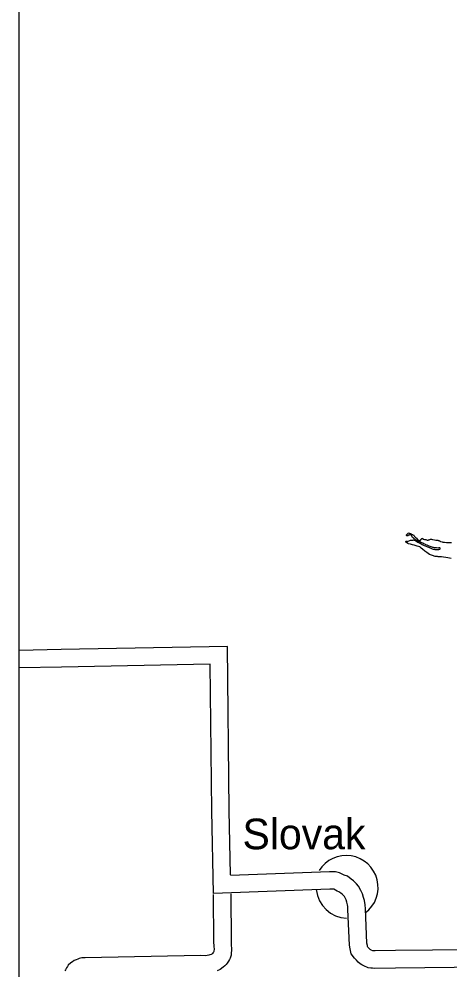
# Model space of a CAD drawing. Extents: x 982240 to 1103002, y 974866 to 1054902.
# Drawn here: x 984683 to 990254, y 1035077 to 1047369 of the extents above; entities that cross this region are included whole.
import ezdxf

# ---------------------------------------------------------------- set-up
doc = ezdxf.new("R2010")
doc.units = 0
for name, color, linetype in [('Level 10', 7, 'Continuous'), ('Level 24', 7, 'Continuous'), ('Level 9', 7, 'Continuous'), ('R_Draft', 7, 'Continuous')]:
    doc.layers.add(name, color=color, linetype=linetype)

msp = doc.modelspace()

# ---------------------------------------------------------------- linework, layer by layer
at = {"layer": 'Level 10'}
for points in [[(987416, 1036306), (987401, 1037140), (987377, 1039260), (985227, 1039218), (984683, 1039207)], [(987195, 1036066), (987176, 1037136), (987155, 1039031), (985231, 1038993), (984683, 1038982)], [(991462, 1035348), (989548, 1035328), (989285, 1035324), (989269, 1035325), (989255, 1035326), (989237, 1035333), (989232, 1035336), (989230, 1035337), (989222, 1035344), (989205, 1035360), (989193, 1035373), (989188, 1035380), (989186, 1035392), (989180, 1035424), (989160, 1035866), (989159, 1035920), (989149, 1035975), (989136, 1036015), (989124, 1036060), (989103, 1036106), (989073, 1036160), (989046, 1036189), (989009, 1036229), (988977, 1036251), (988928, 1036289), (988886, 1036304), (988826, 1036335), (988775, 1036345), (988698, 1036345), (987416, 1036299)], [(991451, 1035122), (989551, 1035103), (989278, 1035098), (989254, 1035100), (989233, 1035101), (989198, 1035105), (989140, 1035130), (989116, 1035143), (989092, 1035159), (989068, 1035180), (989045, 1035203), (989020, 1035229), (988978, 1035287), (988965, 1035349), (988956, 1035400), (988935, 1035859), (988935, 1035898), (988931, 1035920), (988920, 1035952), (988912, 1035984), (988903, 1036003), (988890, 1036026), (988881, 1036036), (988861, 1036058), (988844, 1036069), (988819, 1036089), (988797, 1036097), (988752, 1036120), (988701, 1036120), (987195, 1036066)], [(987194, 1036053), (987199, 1035432), (987201, 1035393), (987203, 1035375), (987204, 1035350), (987205, 1035342), (987202, 1035327), (987202, 1035316), (987196, 1035306), (987194, 1035302), (987185, 1035292), (987180, 1035285), (987174, 1035281), (987168, 1035278), (987151, 1035273), (987135, 1035268), (987135, 1035268), (987115, 1035265), (987091, 1035262), (987031, 1035265), (985540, 1035236), (985497, 1035233), (985462, 1035224), (985442, 1035217), (985423, 1035210), (985397, 1035199), (985373, 1035184), (985351, 1035170), (985319, 1035141), (985308, 1035124), (985297, 1035107), (985283, 1035081), (985276, 1035067)], [(987419, 1036061), (987424, 1035439), (987426, 1035407), (987427, 1035390), (987429, 1035364), (987431, 1035325), (987427, 1035303), (987427, 1035267), (987411, 1035231), (987402, 1035214), (987391, 1035191), (987374, 1035167), (987360, 1035150), (987344, 1035130), (987324, 1035112), (987284, 1035083), (987246, 1035068)]]:
    msp.add_lwpolyline(points, dxfattribs=at)
at = {"layer": 'Level 24'}
for centre, start, end in [((988913, 1036145), 306.7405, 148.2665), ((988936, 1036157), 185.7106, 267.4831)]:
    msp.add_arc(centre, 412, start, end, dxfattribs=at)
at = {"layer": 'Level 9'}
for points in [[(989964, 1040548), (989975, 1040542), (989983, 1040539), (989991, 1040537), (990007, 1040530), (990016, 1040526), (990023, 1040523), (990037, 1040518), (990048, 1040515), (990060, 1040512), (990075, 1040511), (990085, 1040512), (990099, 1040512), (990106, 1040513), (990111, 1040514), (990122, 1040516), (990123, 1040517), (990126, 1040523), (990127, 1040528), (990125, 1040532), (990120, 1040535), (990115, 1040534), (990113, 1040533), (990109, 1040532), (990103, 1040530), (990082, 1040532), (990059, 1040533), (990053, 1040533), (990041, 1040537), (990033, 1040538), (990022, 1040541), (990011, 1040545), (989998, 1040550), (989985, 1040555), (989959, 1040567), (989944, 1040573), (989936, 1040577), (989918, 1040586), (989903, 1040593), (989897, 1040596), (989883, 1040603), (989876, 1040605), (989867, 1040609), (989855, 1040614), (989851, 1040615), (989843, 1040619), (989835, 1040625), (989827, 1040628), (989819, 1040632), (989809, 1040639), (989800, 1040645), (989793, 1040650), (989786, 1040655), (989782, 1040658), (989769, 1040668), (989764, 1040677), (989762, 1040684), (989758, 1040693), (989748, 1040700), (989736, 1040702), (989731, 1040700), (989725, 1040698), (989720, 1040696), (989715, 1040695), (989710, 1040691), (989704, 1040689), (989700, 1040689), (989698, 1040689), (989696, 1040690), (989694, 1040694), (989694, 1040696), (989694, 1040703), (989699, 1040707), (989702, 1040711), (989704, 1040713), (989708, 1040717), (989715, 1040722), (989721, 1040726), (989726, 1040725), (989733, 1040721), (989742, 1040718), (989750, 1040715), (989752, 1040714), (989755, 1040712), (989765, 1040707), (989769, 1040705), (989772, 1040703), (989778, 1040702), (989782, 1040700), (989788, 1040694), (989791, 1040688), (989795, 1040684), (989796, 1040682), (989799, 1040676), (989802, 1040672), (989807, 1040669), (989809, 1040667), (989814, 1040664), (989819, 1040662), (989824, 1040660), (989827, 1040655)], [(989827, 1040655), (989828, 1040651), (989830, 1040646), (989836, 1040642), (989859, 1040630), (989865, 1040628), (989867, 1040628), (989869, 1040629), (989872, 1040630), (989873, 1040632), (989875, 1040635), (989878, 1040640), (989880, 1040643), (989882, 1040646), (989884, 1040648), (989886, 1040651), (989889, 1040655), (989893, 1040656), (989895, 1040658), (989898, 1040656), (989903, 1040653), (989904, 1040651), (989908, 1040648), (989911, 1040647), (989926, 1040642), (989942, 1040640), (989959, 1040633), (989970, 1040634), (989978, 1040636), (989986, 1040638), (989992, 1040643), (990002, 1040645), (990016, 1040644), (990030, 1040642), (990053, 1040639), (990073, 1040635), (990091, 1040633), (990097, 1040632), (990103, 1040630), (990112, 1040627), (990120, 1040623), (990124, 1040621), (990128, 1040620), (990130, 1040618), (990138, 1040614), (990151, 1040611), (990163, 1040608), (990184, 1040607), (990210, 1040605), (990251, 1040604), (990275, 1040602)], [(990268, 1040395), (990228, 1040404), (990202, 1040410), (990171, 1040414), (990144, 1040416), (990127, 1040417), (990103, 1040419), (990092, 1040420), (990064, 1040424), (990030, 1040433), (989989, 1040449), (989954, 1040474), (989929, 1040493), (989901, 1040516), (989882, 1040531), (989873, 1040539), (989871, 1040541), (989863, 1040549), (989830, 1040557), (989789, 1040570), (989769, 1040574), (989742, 1040581), (989720, 1040586), (989710, 1040588), (989690, 1040603), (989685, 1040606), (989683, 1040612), (989684, 1040616), (989688, 1040619), (989695, 1040620), (989706, 1040618), (989712, 1040619), (989736, 1040628), (989745, 1040632), (989753, 1040634), (989762, 1040635), (989770, 1040635), (989774, 1040635), (989778, 1040635), (989783, 1040636), (989811, 1040625), (989840, 1040609), (989857, 1040598), (989882, 1040587), (989895, 1040578), (989921, 1040565), (989948, 1040555), (989964, 1040548)]]:
    msp.add_lwpolyline(points, dxfattribs=at)
at = {"layer": 'R_Draft'}
msp.add_lwpolyline([(984683, 1051554), (1006582, 1051554), (1006582, 1032484), (984683, 1032484)], close=True, dxfattribs=at)

# ---------------------------------------------------------------- texts
at = {"layer": 'Level 24'}
msp.add_text('Slovak', height=396, dxfattribs=at).set_placement((987572, 1036638))

doc.saveas('drawing.dxf')
